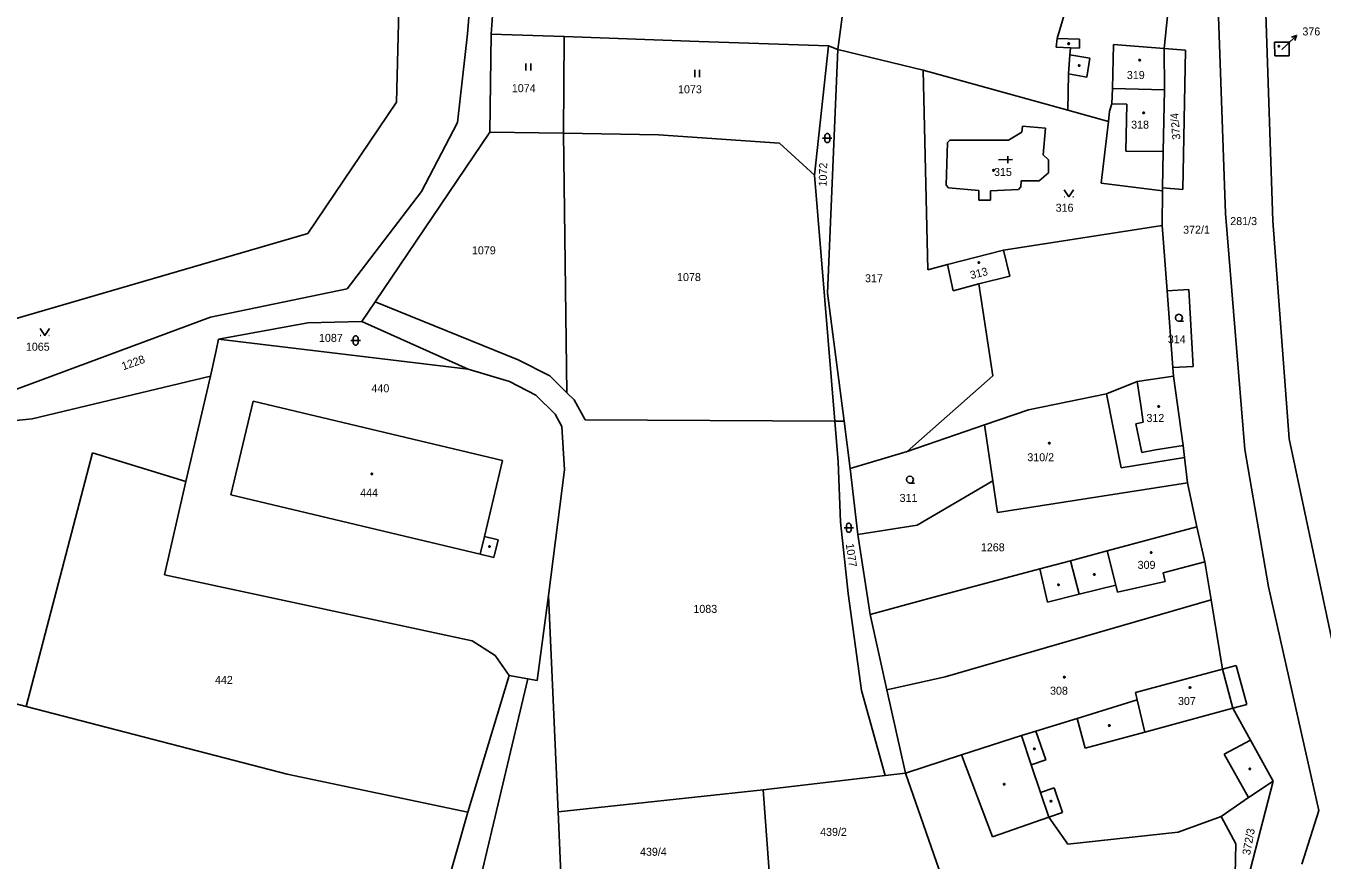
# Model space of a CAD drawing. Extents: x -812394 to -807601, y -1013097 to -1009266.
# Drawn here: x -811273.1 to -810997.7, y -1011589.1 to -1011411.9 of the extents above; entities that cross this region are included whole.
import ezdxf

# ---------------------------------------------------------------- set-up
doc = ezdxf.new("R2010")
doc.units = 0
for name, color, linetype in [('Default', 7, 'Continuous'), ('KN_HRANICE', 7, 'Continuous'), ('KN_KULTURY', 7, 'Continuous'), ('KN_PARCELY', 7, 'Continuous'), ('KN_SLUCKY', 7, 'Continuous')]:
    doc.layers.add(name, color=color, linetype=linetype)

# ---------------------------------------------------------------- blocks, each defined once
blk = doc.blocks.new('10292')
at = {"layer": 'Default'}
blk.add_line((0, 3), (0, 0), dxfattribs=at)
blk.add_lwpolyline([(-0.5, 2), (0, 3), (0.5, 2)], dxfattribs=at)
blk = doc.blocks.new('304')
at = {"layer": 'Default'}
blk.add_lwpolyline([(0, 0), (-0.38, 0.1), (-0.65, 0.37), (-0.75, 0.74), (-0.65, 1.11), (-0.38, 1.38), (-0.01, 1.48), (0.36, 1.38), (0.63, 1.11), (0.73, 0.73), (0.63, 0.35), (0.36, 0.08), (-0.02, -0.02), (0.98, -0.02)], dxfattribs=at)
blk = doc.blocks.new('306')
at = {"layer": 'Default'}
for p, q in [((-0.5, 1.5), (-0.5, 0)), ((0.5, 0), (0.5, 1.5))]:
    blk.add_line(p, q, dxfattribs=at)
blk = doc.blocks.new('314')
at = {"layer": 'Default'}
for p, q in [((-0.95, 0), (-0.85, 0)), ((0.85, 0), (0.95, 0))]:
    blk.add_line(p, q, dxfattribs=at)
blk.add_lwpolyline([(-1, 1.5), (0, 0), (1, 1.5)], dxfattribs=at)
blk = doc.blocks.new('316')
at = {"layer": 'Default'}
for points in [[(-1, 1), (0.27, 1), (1, 1)], [(-0.5, 1.5), (-0.4, 1.79), (-0.15, 1.97), (0.16, 1.97), (0.41, 1.79), (0.51, 1.5), (0.51, 0.5), (0.41, 0.21), (0.16, 0.03), (-0.15, 0.03), (-0.4, 0.21), (-0.5, 0.5), (-0.5, 1.5)]]:
    blk.add_lwpolyline(points, dxfattribs=at)
blk = doc.blocks.new('NAHRADNI_SYMBOL')
at = {"layer": 'Default'}
blk.add_lwpolyline([(0.09, 0.15), (0.18, 0), (0.09, -0.15), (-0.09, -0.15), (-0.18, 0), (-0.09, 0.15), (0.09, 0.15)], dxfattribs=at)
blk = doc.blocks.new('402')
at = {"layer": 'Default'}
blk.add_lwpolyline([(0.09, 0.15), (0.18, 0), (0.09, -0.15), (-0.09, -0.15), (-0.18, 0), (-0.09, 0.15), (0.09, 0.15)], dxfattribs=at)
blk = doc.blocks.new('4091')
at = {"layer": 'Default'}
for p, q in [((0, 0), (0, 3)), ((0.75, 2), (-0.75, 2))]:
    blk.add_line(p, q, dxfattribs=at)

msp = doc.modelspace()

# ---------------------------------------------------------------- linework, layer by layer
at = {"layer": 'KN_HRANICE'}
for p, q in [((-811194.35, -1011428.07), (-811191.38, -1011303.47)), ((-811172.89, -1011326.55), (-811179.25, -1011413.51)), ((-811174.26, -1011413.61), (-811170.58, -1011363.44)), ((-811096.21, -1011383.14), (-811100.57, -1011416.83)), ((-811054.01, -1011414.53), (-811051.11, -1011404.88)), ((-811031.22, -1011416.63), (-811030.55, -1011409.8)), ((-811018.24, -1011451.73), (-811019.73, -1011409.84)), ((-811008.13, -1011453.24), (-811009.67, -1011409.19)), ((-811179.25, -1011413.51), (-811181.37, -1011432.37)), ((-811174.5, -1011434.42), (-811174.26, -1011413.61)), ((-811174.26, -1011413.61), (-811158.74, -1011414.11)), ((-811158.74, -1011414.11), (-811158.86, -1011434.66)), ((-811130.11, -1011415.14), (-811158.74, -1011414.11)), ((-811102.55, -1011416.12), (-811130.11, -1011415.14)), ((-811054.16, -1011416.37), (-811054.01, -1011414.53)), ((-811007.8, -1011415.34), (-811004.69, -1011415.34)), ((-811007.76, -1011418.21), (-811007.8, -1011415.34)), ((-811004.69, -1011415.34), (-811004.69, -1011418.19)), ((-811105.53, -1011443.55), (-811102.55, -1011416.12)), ((-811100.57, -1011416.83), (-811102.76, -1011468.61)), ((-811100.57, -1011416.83), (-811102.55, -1011416.12)), ((-811100.57, -1011416.83), (-811082.43, -1011421.27)), ((-811051.17, -1011416.5), (-811054.16, -1011416.37)), ((-811051.58, -1011422.05), (-811051.28, -1011418.03)), ((-811051.28, -1011418.03), (-811051.17, -1011416.5)), ((-811042.21, -1011425.17), (-811042.03, -1011415.82)), ((-811042.03, -1011415.82), (-811031.22, -1011416.63)), ((-811026.7, -1011416.99), (-811031.22, -1011416.63)), ((-811031.22, -1011416.63), (-811031.17, -1011425.43)), ((-811027.28, -1011446.6), (-811026.7, -1011416.99)), ((-811004.69, -1011418.19), (-811007.76, -1011418.21)), ((-811082.43, -1011421.27), (-811081.48, -1011463.7)), ((-811082.43, -1011421.27), (-811051.74, -1011429.77)), ((-811051.74, -1011429.77), (-811051.58, -1011422.05)), ((-811042.36, -1011428.43), (-811042.21, -1011425.17)), ((-811042.21, -1011425.17), (-811031.17, -1011425.43)), ((-811031.17, -1011425.43), (-811031.47, -1011438.51)), ((-811213.2, -1011455.92), (-811194.35, -1011428.07)), ((-811042.83, -1011429.97), (-811042.36, -1011428.43)), ((-811051.74, -1011429.77), (-811043.09, -1011432.16)), ((-811043.09, -1011432.16), (-811042.83, -1011429.97)), ((-811198.88, -1011470.45), (-811174.5, -1011434.42)), ((-811181.37, -1011432.37), (-811189.07, -1011447.02)), ((-811174.5, -1011434.42), (-811158.86, -1011434.66)), ((-811158.86, -1011434.66), (-811158.14, -1011489.78)), ((-811064.35, -1011436.14), (-811061.46, -1011434.46)), ((-811061.46, -1011434.46), (-811061.38, -1011433.17)), ((-811061.38, -1011433.17), (-811056.43, -1011433.57)), ((-811056.43, -1011433.57), (-811056.94, -1011439.23)), ((-811044.66, -1011445.25), (-811043.09, -1011432.16)), ((-811077.55, -1011445.67), (-811077.3, -1011436.6)), ((-811077.3, -1011436.6), (-811076.77, -1011436.14)), ((-811076.77, -1011436.14), (-811064.35, -1011436.14)), ((-811056.94, -1011439.23), (-811055.82, -1011440.32)), ((-811055.82, -1011440.32), (-811055.82, -1011443.07)), ((-811031.47, -1011438.51), (-811031.57, -1011446.26)), ((-811055.82, -1011443.07), (-811057.83, -1011444.74)), ((-811101.25, -1011495.79), (-811105.53, -1011443.55)), ((-811077.04, -1011446.24), (-811077.55, -1011445.67)), ((-811061.64, -1011444.79), (-811061.68, -1011446.05)), ((-811057.83, -1011444.74), (-811061.64, -1011444.79)), ((-811031.58, -1011446.91), (-811044.66, -1011445.25)), ((-811189.07, -1011447.02), (-811204.87, -1011467.74)), ((-811070.62, -1011446.79), (-811077.04, -1011446.24)), ((-811070.65, -1011448.85), (-811070.62, -1011446.79)), ((-811062.21, -1011446.58), (-811068.18, -1011446.87)), ((-811068.18, -1011446.87), (-811068.16, -1011448.89)), ((-811061.68, -1011446.05), (-811062.21, -1011446.58)), ((-811031.68, -1011454.25), (-811031.58, -1011446.91)), ((-811031.58, -1011446.91), (-811031.57, -1011446.26)), ((-811031.57, -1011446.26), (-811027.28, -1011446.6)), ((-811068.16, -1011448.89), (-811070.65, -1011448.85)), ((-811014.13, -1011501.83), (-811018.24, -1011451.73)), ((-811004.66, -1011499.57), (-811008.13, -1011453.24)), ((-811303.93, -1011482.35), (-811213.2, -1011455.92)), ((-811065.4, -1011459.51), (-811031.68, -1011454.25)), ((-811030.62, -1011468.1), (-811031.68, -1011454.25)), ((-811077.31, -1011462.56), (-811065.4, -1011459.51)), ((-811081.48, -1011463.7), (-811077.31, -1011462.56)), ((-811076.05, -1011468.17), (-811077.31, -1011462.56)), ((-811204.87, -1011467.74), (-811233.91, -1011473.74)), ((-811070.65, -1011466.68), (-811076.05, -1011468.17)), ((-811067.64, -1011486.22), (-811070.65, -1011466.68)), ((-811025.99, -1011467.86), (-811030.62, -1011468.1)), ((-811025.07, -1011484.23), (-811025.99, -1011467.86)), ((-811201.72, -1011474.65), (-811198.88, -1011470.45)), ((-811168.48, -1011482.77), (-811198.88, -1011470.45)), ((-811102.76, -1011468.61), (-811099.25, -1011495.85)), ((-811029.37, -1011484.43), (-811030.62, -1011468.1)), ((-811233.91, -1011473.74), (-811289.1, -1011494.23)), ((-811232.17, -1011478.43), (-811213.22, -1011474.91)), ((-811213.22, -1011474.91), (-811201.72, -1011474.65)), ((-811201.72, -1011474.65), (-811179.11, -1011484.8)), ((-811232.17, -1011478.43), (-811232.72, -1011480.8)), ((-811179.11, -1011484.8), (-811232.17, -1011478.43)), ((-811232.72, -1011480.8), (-811233.91, -1011486.25)), ((-811161.78, -1011486.19), (-811168.48, -1011482.77)), ((-811025.07, -1011484.23), (-811029.37, -1011484.43)), ((-811029.37, -1011484.43), (-811029.23, -1011486.26)), ((-811233.91, -1011486.25), (-811271.79, -1011495.36)), ((-811233.91, -1011486.25), (-811239.11, -1011508.63)), ((-811170.35, -1011487.43), (-811179.11, -1011484.8)), ((-811158.14, -1011489.78), (-811161.78, -1011486.19)), ((-811085.84, -1011502.26), (-811067.64, -1011486.22)), ((-811036.96, -1011487.4), (-811029.23, -1011486.26)), ((-811029.23, -1011486.26), (-811027.21, -1011501.02)), ((-811164.74, -1011490.29), (-811170.35, -1011487.43)), ((-811158.14, -1011489.78), (-811156.58, -1011491.32)), ((-811043.53, -1011490.02), (-811036.96, -1011487.4)), ((-811229.57, -1011511.44), (-811224.84, -1011491.55)), ((-811224.84, -1011491.55), (-811171.82, -1011504.19)), ((-811160.62, -1011494.36), (-811164.74, -1011490.29)), ((-811156.58, -1011491.32), (-811154.29, -1011495.54)), ((-811060.1, -1011493.41), (-811043.53, -1011490.02)), ((-811043.53, -1011490.02), (-811040.39, -1011505.73)), ((-811271.79, -1011495.36), (-811280.14, -1011496.2)), ((-811159.21, -1011496.95), (-811160.62, -1011494.36)), ((-811069.41, -1011496.61), (-811060.1, -1011493.41)), ((-811158.66, -1011506.17), (-811159.21, -1011496.95)), ((-811154.29, -1011495.54), (-811101.25, -1011495.79)), ((-811099.25, -1011495.85), (-811101.25, -1011495.79)), ((-811101.25, -1011495.79), (-811100.54, -1011504.44)), ((-811099.25, -1011495.85), (-811097.96, -1011505.89)), ((-811085.84, -1011502.26), (-811069.41, -1011496.61)), ((-811067.66, -1011508.49), (-811069.41, -1011496.61)), ((-810988.29, -1011576.92), (-811004.66, -1011499.57)), ((-811258.94, -1011502.58), (-811273.05, -1011556.43)), ((-811239.11, -1011508.63), (-811258.94, -1011502.58)), ((-811097.96, -1011505.89), (-811085.84, -1011502.26)), ((-811040.39, -1011505.73), (-811026.92, -1011503.52)), ((-811026.92, -1011503.52), (-811027.21, -1011501.02)), ((-811026.29, -1011508.89), (-811026.92, -1011503.52)), ((-811009.09, -1011531.03), (-811014.13, -1011501.83)), ((-811171.82, -1011504.19), (-811175.7, -1011520.33)), ((-811162.1, -1011532.85), (-811158.66, -1011506.17)), ((-811100.54, -1011504.44), (-811100.02, -1011517.23)), ((-811097.96, -1011505.89), (-811096.31, -1011519.91)), ((-811239.11, -1011508.63), (-811243.65, -1011528.46)), ((-811083.76, -1011517.9), (-811067.66, -1011508.49)), ((-811066.67, -1011515.22), (-811067.66, -1011508.49)), ((-811026.29, -1011508.89), (-811066.67, -1011515.22)), ((-811024.27, -1011518.27), (-811026.29, -1011508.89)), ((-811176.6, -1011524.08), (-811229.57, -1011511.44)), ((-811100.02, -1011517.23), (-811098.41, -1011532.42)), ((-811096.31, -1011519.91), (-811083.76, -1011517.9)), ((-811096.31, -1011519.91), (-811093.69, -1011536.91)), ((-811043.33, -1011523.37), (-811024.27, -1011518.27)), ((-811022.62, -1011525.72), (-811024.27, -1011518.27)), ((-811172.77, -1011521.02), (-811175.7, -1011520.33)), ((-811173.66, -1011524.78), (-811172.77, -1011521.02)), ((-811176.6, -1011524.08), (-811173.66, -1011524.78)), ((-811057.69, -1011527.22), (-811051.12, -1011525.46)), ((-811051.12, -1011525.46), (-811043.33, -1011523.37)), ((-811021.28, -1011533.77), (-811022.62, -1011525.72)), ((-811243.65, -1011528.46), (-811178.27, -1011542.52)), ((-811081.24, -1011533.53), (-811057.69, -1011527.22)), ((-810998.41, -1011578.57), (-811009.09, -1011531.03)), ((-811164.49, -1011550.91), (-811162.1, -1011532.85)), ((-811159.98, -1011578.81), (-811162.1, -1011532.85)), ((-811098.41, -1011532.42), (-811095.53, -1011553.04)), ((-811081.24, -1011533.53), (-811093.69, -1011536.91)), ((-811077.76, -1011550.14), (-811021.28, -1011533.77)), ((-811018.83, -1011548.49), (-811021.28, -1011533.77)), ((-811093.69, -1011536.91), (-811090.2, -1011552.87)), ((-811178.27, -1011542.52), (-811173.42, -1011545.58)), ((-811173.42, -1011545.58), (-811170.39, -1011549.84)), ((-811018.83, -1011548.49), (-811015.93, -1011547.71)), ((-811015.93, -1011547.71), (-811013.7, -1011556.01)), ((-811301.11, -1011549.16), (-811273.05, -1011556.43)), ((-811179.22, -1011578.9), (-811170.39, -1011549.84)), ((-811178.18, -1011599.83), (-811166.46, -1011550.55)), ((-811170.39, -1011549.84), (-811166.46, -1011550.55)), ((-811166.46, -1011550.55), (-811164.49, -1011550.91)), ((-811090.2, -1011552.87), (-811077.76, -1011550.14)), ((-811037.35, -1011553.47), (-811018.83, -1011548.49)), ((-811095.53, -1011553.04), (-811090.56, -1011571.12)), ((-811090.2, -1011552.87), (-811086.24, -1011570.61)), ((-811049.73, -1011558.97), (-811036.98, -1011555.03)), ((-811036.98, -1011555.03), (-811037.35, -1011553.47)), ((-811013.7, -1011556.01), (-811016.66, -1011556.83)), ((-811273.05, -1011556.43), (-811217.62, -1011570.79)), ((-811012.91, -1011563.56), (-811016.66, -1011556.83)), ((-811058.48, -1011561.67), (-811049.73, -1011558.97)), ((-811074.28, -1011566.74), (-811061.54, -1011562.61)), ((-811061.54, -1011562.61), (-811058.48, -1011561.67)), ((-811008.1, -1011572.3), (-811012.91, -1011563.56)), ((-811086.24, -1011570.61), (-811074.28, -1011566.74)), ((-811074.28, -1011566.74), (-811067.73, -1011584.15)), ((-811217.62, -1011570.79), (-811179.22, -1011578.9)), ((-811090.56, -1011571.12), (-811116.42, -1011574.14)), ((-811086.24, -1011570.61), (-811090.56, -1011571.12)), ((-811078.55, -1011592.58), (-811086.24, -1011570.61)), ((-811008.1, -1011572.3), (-811015.03, -1011599.04)), ((-811008.1, -1011572.3), (-811013.29, -1011575.78)), ((-811116.42, -1011574.14), (-811159.98, -1011578.81)), ((-811114.74, -1011597.01), (-811116.42, -1011574.14)), ((-811013.29, -1011575.78), (-811019.13, -1011579.83)), ((-811186.53, -1011604.51), (-811179.22, -1011578.9)), ((-811159.98, -1011578.81), (-811159.05, -1011601.95)), ((-811067.73, -1011584.15), (-811055.76, -1011579.97)), ((-811055.76, -1011579.97), (-811051.71, -1011585.72)), ((-811028.3, -1011583.16), (-811019.13, -1011579.83)), ((-811019.13, -1011579.83), (-811016.02, -1011585.65)), ((-811001.99, -1011589.96), (-810998.41, -1011578.57)), ((-811051.71, -1011585.72), (-811028.3, -1011583.16)), ((-811016.02, -1011585.65), (-811016.27, -1011596.11))]:
    msp.add_line(p, q, dxfattribs=at)
msp.add_lwpolyline([(-811158.86, -1011434.66), (-811138.69, -1011434.98), (-811112.99, -1011436.74), (-811105.53, -1011443.55)], dxfattribs=at)
at = {"layer": 'KN_PARCELY'}
msp.add_line((-811006.23, -1011416.88), (-811005.27, -1011415.96), dxfattribs=at)
at = {"layer": 'KN_SLUCKY'}
for p, q in [((-811054.01, -1011414.53), (-811049.22, -1011414.7)), ((-811049.22, -1011414.7), (-811049.26, -1011416.58)), ((-811051.28, -1011418.03), (-811047.03, -1011418.74)), ((-811051.17, -1011416.5), (-811049.26, -1011416.58)), ((-811047.71, -1011422.71), (-811047.03, -1011418.74)), ((-811051.58, -1011422.05), (-811047.71, -1011422.71)), ((-811039.18, -1011428.46), (-811042.36, -1011428.43)), ((-811039.38, -1011438.44), (-811039.18, -1011428.46)), ((-811031.47, -1011438.51), (-811039.38, -1011438.44)), ((-811064.03, -1011465.05), (-811065.4, -1011459.51)), ((-811064.03, -1011465.05), (-811070.65, -1011466.68)), ((-811036.15, -1011492.95), (-811036.96, -1011487.4)), ((-811035.7, -1011496.05), (-811036.15, -1011492.95)), ((-811037.28, -1011496.38), (-811035.7, -1011496.05)), ((-811036.01, -1011502.47), (-811037.28, -1011496.38)), ((-811033.05, -1011501.88), (-811036.01, -1011502.47)), ((-811027.21, -1011501.02), (-811033.05, -1011501.88)), ((-811175.7, -1011520.33), (-811176.6, -1011524.08)), ((-811049.33, -1011532.61), (-811051.12, -1011525.46)), ((-811041.5, -1011530.65), (-811043.33, -1011523.37)), ((-811022.62, -1011525.72), (-811031.45, -1011528.02)), ((-811056, -1011534.29), (-811057.69, -1011527.22)), ((-811031.03, -1011529.88), (-811031.45, -1011528.02)), ((-811049.33, -1011532.61), (-811041.5, -1011530.65)), ((-811041.5, -1011530.65), (-811041.13, -1011532.12)), ((-811031.03, -1011529.88), (-811041.13, -1011532.12)), ((-811056, -1011534.29), (-811049.33, -1011532.61)), ((-811018.83, -1011548.49), (-811016.66, -1011556.83)), ((-811036.98, -1011555.03), (-811035.34, -1011561.89)), ((-811016.66, -1011556.83), (-811035.34, -1011561.89)), ((-811048.01, -1011565.32), (-811049.73, -1011558.97)), ((-811059.48, -1011568.8), (-811061.54, -1011562.61)), ((-811058.48, -1011561.67), (-811056.41, -1011567.76)), ((-811035.34, -1011561.89), (-811048.01, -1011565.32)), ((-811012.91, -1011563.56), (-811018.46, -1011566.59)), ((-811018.46, -1011566.59), (-811013.29, -1011575.78)), ((-811056.41, -1011567.76), (-811059.48, -1011568.8)), ((-811057.5, -1011574.74), (-811059.48, -1011568.8)), ((-811054.65, -1011573.74), (-811057.5, -1011574.74)), ((-811055.76, -1011579.97), (-811057.5, -1011574.74)), ((-811052.83, -1011578.95), (-811054.65, -1011573.74)), ((-811055.76, -1011579.97), (-811052.83, -1011578.95))]:
    msp.add_line(p, q, dxfattribs=at)

# ---------------------------------------------------------------- block references
at = {"layer": 'KN_KULTURY'}
for name, p in [('402', (-811051.54, -1011415.62)), ('402', (-811006.87, -1011416.17)), ('306', (-811166.35, -1011421.36)), ('402', (-811049.32, -1011420.27)), ('NAHRADNI_SYMBOL', (-811036.46, -1011419.11)), ('306', (-811130.47, -1011422.71)), ('402', (-811035.61, -1011430.34)), ('316', (-811102.83, -1011436.68)), ('402', (-811067.5, -1011442.54)), ('314', (-811051.48, -1011448.16)), ('402', (-811070.62, -1011462.14)), ('304', (-811028.11, -1011474.58)), ('314', (-811269.11, -1011477.61)), ('316', (-811203.05, -1011479.68)), ('402', (-811032.4, -1011492.69)), ('NAHRADNI_SYMBOL', (-811055.66, -1011500.48)), ('402', (-811199.61, -1011507.03)), ('304', (-811085.27, -1011508.97)), ('316', (-811098.27, -1011519.47)), ('402', (-811174.59, -1011522.46)), ('402', (-811034, -1011523.75)), ('402', (-811046.09, -1011528.39)), ('402', (-811053.7, -1011530.57)), ('NAHRADNI_SYMBOL', (-811052.45, -1011550.21)), ('402', (-811025.77, -1011552.43)), ('402', (-811042.88, -1011560.48)), ('402', (-811058.82, -1011565.41)), ('402', (-811013.04, -1011569.71)), ('402', (-811065.25, -1011572.96)), ('402', (-811055.3, -1011576.55))]:
    msp.add_blockref(name, p, dxfattribs=at)
at = {"layer": 'KN_KULTURY', "rotation": -89.16284999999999}
msp.add_blockref('4091', (-811066.45, -1011440.29), dxfattribs=at)
at = {"layer": 'KN_PARCELY', "rotation": -46.13372000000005}
msp.add_blockref('10292', (-811005.27, -1011415.96), dxfattribs=at)

# ---------------------------------------------------------------- texts
at = {"layer": 'KN_PARCELY'}
for s, height, p in [('376', 1.7, (-811001.87, -1011413.88)), ('376', 0.1, (-811006.37, -1011416.88)), ('319', 1.7, (-811039.17, -1011423.14)), ('1074', 1.7, (-811169.86, -1011425.93)), ('1073', 1.7, (-811134.54, -1011426.17)), ('318', 1.7, (-811038.26, -1011433.68)), ('315', 1.7, (-811067.39, -1011443.73)), ('316', 1.7, (-811054.3, -1011451.33)), ('281/3', 1.7, (-811017.2, -1011454.17)), ('372/1', 1.7, (-811027.22, -1011455.99)), ('1079', 1.7, (-811178.33, -1011460.38)), ('1078', 1.7, (-811134.75, -1011466.06)), ('317', 1.7, (-811094.81, -1011466.31)), ('1087', 1.7, (-811210.84, -1011478.98)), ('314', 1.7, (-811030.46, -1011479.26)), ('1065', 1.7, (-811273.12, -1011480.86)), ('440', 1.7, (-811199.69, -1011489.69)), ('312', 1.7, (-811035.01, -1011495.99)), ('310/2', 1.7, (-811060.32, -1011504.34)), ('444', 1.7, (-811202.08, -1011511.88)), ('311', 1.7, (-811087.46, -1011512.98)), ('1268', 1.7, (-811070.19, -1011523.47)), ('309', 1.7, (-811036.88, -1011527.2)), ('1083', 1.7, (-811131.28, -1011536.55)), ('442', 1.7, (-811232.94, -1011551.65)), ('308', 1.7, (-811055.49, -1011553.93)), ('307', 1.7, (-811028.31, -1011556.12)), ('439/2', 1.7, (-811104.35, -1011583.93)), ('439/4', 1.7, (-811142.62, -1011588.15))]:
    msp.add_text(s, height=height, dxfattribs=at).set_placement(p)
for s, rotation, p in [('372/4', 94.71, (-811027.79, -1011435.96)), ('1072', 88.465, (-811102.97, -1011445.99)), ('313', 13.923, (-811072.26, -1011465.67)), ('1228', 19.481, (-811252.42, -1011485.03)), ('1077', 277.942, (-811098.9, -1011521.92)), ('372/3', 79.412, (-811013, -1011588.11))]:
    msp.add_text(s, height=1.7, rotation=rotation, dxfattribs=at).set_placement(p)

doc.saveas('drawing.dxf')
